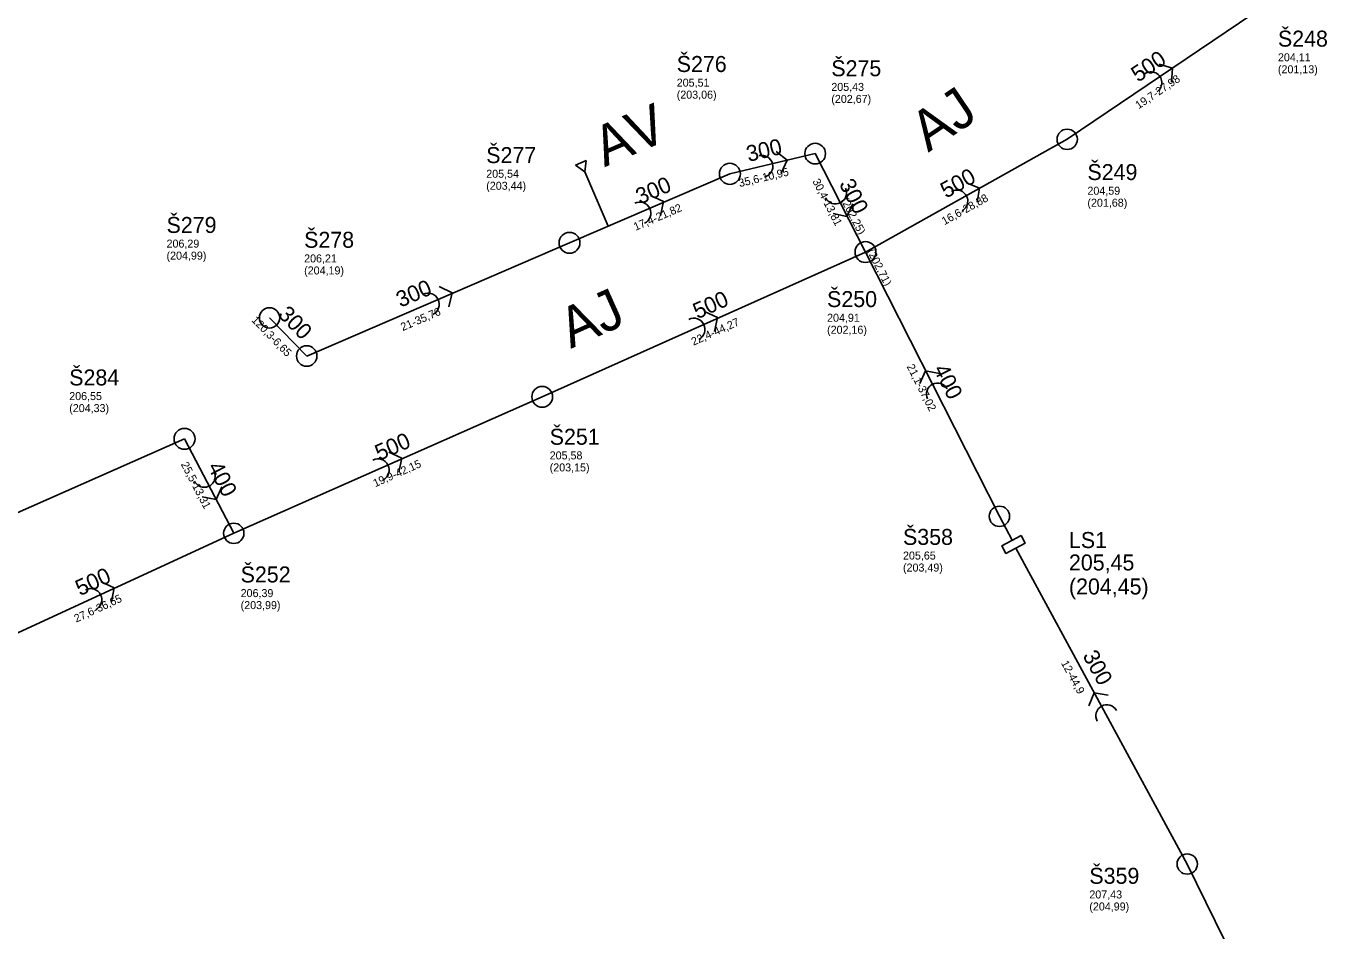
# Model space of a CAD drawing. Extents: x -574467 to -573663, y -1191209 to -1190406.
# Drawn here: x -573973 to -573810.4, y -1190808.6 to -1190695.6 of the extents above; entities that cross this region are included whole.
import ezdxf

# ---------------------------------------------------------------- set-up
doc = ezdxf.new("R2010")
doc.units = 0
for name, color, linetype in [('Vrstva 1', 7, 'Continuous'), ('Vrstva 12', 7, 'Continuous'), ('Vrstva 15', 7, 'Continuous'), ('Vrstva 29', 7, 'Continuous'), ('Vrstva 32', 7, 'Continuous'), ('Vrstva 35', 7, 'Continuous'), ('Vrstva 41', 7, 'Continuous'), ('Vrstva 44', 7, 'Continuous'), ('Vrstva 45', 7, 'Continuous'), ('Vrstva 56', 7, 'Continuous'), ('Vrstva 57', 7, 'Continuous')]:
    doc.layers.add(name, color=color, linetype=linetype)

# ---------------------------------------------------------------- blocks, each defined once
blk = doc.blocks.new('100')
at = {"layer": 'Vrstva 1'}
blk.add_circle((0, 0), 1.27, dxfattribs=at)
blk = doc.blocks.new('106')
at = {"layer": 'Vrstva 1'}
for p, q in [((1.25, 0.72), (0, 0)), ((0, 0), (1.25, -0.72)), ((1.25, -0.72), (1.25, 0.72))]:
    blk.add_line(p, q, dxfattribs=at)
blk = doc.blocks.new('86')
at = {"layer": 'Vrstva 1'}
blk.add_lwpolyline([(0.79, 1.37), (1.89, 0), (0.79, -1.38)], dxfattribs=at)
blk.add_arc((-1.37, 0), 1.37, 270, 90, dxfattribs=at)
blk = doc.blocks.new('91')
at = {"layer": 'Vrstva 1'}
blk.add_lwpolyline([(0.79, 1.37), (1.89, 0), (0.79, -1.38)], dxfattribs=at)
blk.add_arc((-1.37, 0), 1.37, 270, 90, dxfattribs=at)

msp = doc.modelspace()

# ---------------------------------------------------------------- linework, layer by layer
at = {"layer": 'Vrstva 12'}
msp.add_line((-573900.287, -1190720.566), (-573903.193, -1190713.788), dxfattribs=at)
at = {"layer": 'Vrstva 15'}
for p, q in [((-573842.91, -1190709.71), (-573819.72, -1190694.05)), ((-573868.12, -1190723.79), (-573842.91, -1190709.71)), ((-573885.07, -1190714.02), (-573874.41, -1190711.5)), ((-573874.41, -1190711.5), (-573868.12, -1190723.79)), ((-573905.11, -1190722.64), (-573885.07, -1190714.02)), ((-573937.96, -1190736.78), (-573905.11, -1190722.64)), ((-573908.528, -1190741.879), (-573868.12, -1190723.79)), ((-573851.38, -1190756.81), (-573868.12, -1190723.79)), ((-573942.607, -1190732.018), (-573937.96, -1190736.78)), ((-573947.076, -1190758.931), (-573908.528, -1190741.879)), ((-574025.44, -1190778.97), (-573953.23, -1190747.128)), ((-573953.23, -1190747.128), (-573947.076, -1190758.931)), ((-573849.777, -1190759.796), (-573851.38, -1190756.81)), ((-573980.36, -1190774.27), (-573947.076, -1190758.931)), ((-573827.9, -1190800.25), (-573849.338, -1190760.798))]:
    msp.add_line(p, q, dxfattribs=at)
msp.add_lwpolyline([(-573813.849, -1190828.881), (-573813.865, -1190828.843), (-573827.9, -1190800.25)], dxfattribs=at)
at = {"layer": 'Vrstva 32'}
msp.add_lwpolyline([(-573848.678, -1190759.212), (-573851.068, -1190760.482), (-573850.558, -1190761.442), (-573848.168, -1190760.172), (-573848.678, -1190759.212)], dxfattribs=at)

# ---------------------------------------------------------------- block references
at = {"layer": 'Vrstva 12', "xscale": 0.9999999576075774, "yscale": 0.9999999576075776, "rotation": 113.00000088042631}
msp.add_blockref('106', (-573903.193, -1190713.788), dxfattribs=at)
at = {"layer": 'Vrstva 29'}
for p, xscale, yscale, rotation in [((-573842.91, -1190709.71), 0.9999999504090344, 0.9999999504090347, -148.99999841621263), ((-573874.41, -1190711.5), 1.0169561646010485, 1.0169561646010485, 153.0239835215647), ((-573885.07, -1190714.02), 1.035124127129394, 1.0351241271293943, -157.49634583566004), ((-573905.11, -1190722.64), 1.025136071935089, 1.0251360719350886, -154.74924162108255), ((-573868.12, -1190723.79), 1.0296949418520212, 1.0296949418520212, -24.133789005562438), ((-573942.607, -1190732.018), 0.9999999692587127, 0.9999999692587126, 133.99999919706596), ((-573937.96, -1190736.78), 1.0060666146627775, 1.0060666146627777, 167.3452647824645), ((-573908.528, -1190741.879), 1.022584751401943, 1.022584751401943, -154.18102569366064), ((-573953.23, -1190747.128), 1.0316957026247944, 1.0316957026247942, 156.4154111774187), ((-573851.38, -1190756.81), 0.999999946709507, 0.999999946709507, -62.999999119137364), ((-573947.076, -1190758.931), 0.9999999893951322, 0.9999999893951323, -109.99999905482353), ((-573827.9, -1190800.25), 0.9999999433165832, 0.999999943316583, -64.0000000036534)]:
    msp.add_blockref('100', p, dxfattribs=dict(at, xscale=xscale, yscale=yscale, rotation=rotation))
at = {"layer": 'Vrstva 41'}
for name, p, xscale, yscale, rotation in [('91', (-573831.315, -1190701.88), 0.9999999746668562, 0.999999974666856, 34.00000045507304), ('86', (-573879.74, -1190712.76), 1.0028916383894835, 1.0028916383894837, 13.697207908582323), ('91', (-573855.515, -1190716.75), 1.0037041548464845, 1.0037041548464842, 29.379208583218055), ('86', (-573895.09, -1190718.33), 1.022584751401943, 1.022584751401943, 25.818974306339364), ('86', (-573871.265, -1190717.645), 0.9999999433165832, 0.999999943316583, -64.0000000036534), ('86', (-573921.535, -1190729.71), 1.022584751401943, 1.022584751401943, 25.818974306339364), ('91', (-573888.324, -1190732.834), 1.0198568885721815, 1.0198568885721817, 26.39398240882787), ('86', (-573859.75, -1190740.3), 0.999999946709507, 0.999999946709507, 117.00000088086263), ('91', (-573927.802, -1190750.405), 1.0198568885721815, 1.0198568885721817, 26.39398240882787), ('86', (-573950.153, -1190753.03), 0.999999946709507, 0.999999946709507, -62.999999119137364), ('91', (-573963.718, -1190766.601), 1.0169561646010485, 1.0169561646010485, 26.97601647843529), ('86', (-573838.619, -1190780.524), 0.999999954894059, 0.9999999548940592, 119.00000058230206)]:
    msp.add_blockref(name, p, dxfattribs=dict(at, xscale=xscale, yscale=yscale, rotation=rotation))

# ---------------------------------------------------------------- texts
at = {"layer": 'Vrstva 32'}
for s, p in [('LS1', (-573842.691, -1190760.771)), ('205,45 ', (-573842.691, -1190763.571)), ('(204,45)', (-573842.691, -1190766.571))]:
    msp.add_text(s, height=2, dxfattribs=at).set_placement(p)
at = {"layer": 'Vrstva 35'}
for s, rotation, p in [('AJ', 34.03, (-573860.278, -1190711.393)), ('AV', 23.29, (-573900.739, -1190713.208)), ('AJ', 24.12, (-573904.956, -1190735.894))]:
    msp.add_text(s, height=5, rotation=rotation, dxfattribs=at).set_placement(p)
at = {"layer": 'Vrstva 44'}
for s, rotation, p in [('500', 34.03, (-573834.054, -1190702.648)), ('300', 13.3, (-573882.743, -1190712.54)), ('300', 23.27, (-573896.303, -1190717.87)), ('300', 297.1, (-573871.466, -1190715.262)), ('500', 29.18, (-573858.041, -1190717.128)), ('300', 23.29, (-573926.241, -1190730.754)), ('500', 24.12, (-573889.121, -1190732.204)), ('300', 314.3, (-573941.656, -1190731.701)), ('400', 296.88, (-573859.686, -1190738.421)), ('500', 23.86, (-573928.876, -1190749.894)), ('400', 297.54, (-573950.4, -1190750.615)), ('500', 24.74, (-573966.293, -1190766.8)), ('300', 298.52, (-573841.029, -1190774.2))]:
    msp.add_text(s, height=2, rotation=rotation, dxfattribs=at).set_placement(p)
at = {"layer": 'Vrstva 45'}
for s, rotation, p in [('19,7-27,98', 34.03, (-573833.98, -1190705.971)), ('35,6-10,95', 13.3, (-573883.847, -1190715.682)), ('30,4-13,81', 297.1, (-573874.781, -1190714.938)), ('17,4-21,82', 23.27, (-573896.844, -1190721.151)), ('(202,25)', 297.1, (-573871.221, -1190717.289)), ('16,6-28,88', 29.18, (-573858.252, -1190720.452)), ('(202,71)', 296.88, (-573867.941, -1190723.699)), ('21-35,76', 23.29, (-573925.955, -1190733.679)), ('120,3-6,65', 314.3, (-573944.918, -1190732.37)), ('22,4-44,27', 24.12, (-573889.62, -1190735.5)), ('21,1-37,02', 296.88, (-573862.997, -1190738.089)), ('25,5-13,31', 297.54, (-573953.711, -1190750.309)), ('19,9-42,15', 23.86, (-573929.395, -1190753.185)), ('27,6-36,65', 24.74, (-573966.758, -1190770.097)), ('12-44,9', 298.52, (-573843.71, -1190775.139))]:
    msp.add_text(s, height=1, rotation=rotation, dxfattribs=at).set_placement(p)
at = {"layer": 'Vrstva 56'}
for s, p in [('204,11 ', (-573816.57, -1190699.96)), ('(201,13)', (-573816.57, -1190701.46)), ('205,51 ', (-573891.71, -1190703.13)), ('205,43 ', (-573872.39, -1190703.66)), ('(203,06)', (-573891.71, -1190704.63)), ('(202,67)', (-573872.39, -1190705.16)), ('205,54 ', (-573915.52, -1190714.51)), ('(203,44)', (-573915.52, -1190716.01)), ('204,59 ', (-573840.38, -1190716.63)), ('(201,68)', (-573840.38, -1190718.13)), ('206,29 ', (-573955.477, -1190723.238)), ('(204,99)', (-573955.477, -1190724.738)), ('206,21 ', (-573938.28, -1190725.09)), ('(204,19)', (-573938.28, -1190726.59)), ('204,91 ', (-573872.92, -1190732.5)), ('(202,16)', (-573872.92, -1190734)), ('206,55 ', (-573967.64, -1190742.288)), ('(204,33)', (-573967.64, -1190743.788)), ('205,58 ', (-573907.588, -1190749.699)), ('(203,15)', (-573907.588, -1190751.199)), ('205,65 ', (-573863.43, -1190762.21)), ('(203,49)', (-573863.43, -1190763.71)), ('206,39 ', (-573946.216, -1190766.901)), ('(203,99)', (-573946.216, -1190768.401)), ('207,43 ', (-573840.14, -1190804.55)), ('(204,99)', (-573840.14, -1190806.05))]:
    msp.add_text(s, height=1, dxfattribs=at).set_placement(p)
at = {"layer": 'Vrstva 57'}
for s, p in [('Š248', (-573816.57, -1190698.13)), ('Š276', (-573891.71, -1190701.3)), ('Š275', (-573872.39, -1190701.83)), ('Š277', (-573915.52, -1190712.68)), ('Š249', (-573840.38, -1190714.8)), ('Š279', (-573955.477, -1190721.408)), ('Š278', (-573938.28, -1190723.26)), ('Š250', (-573872.92, -1190730.67)), ('Š284', (-573967.64, -1190740.458)), ('Š251', (-573907.588, -1190747.869)), ('Š358', (-573863.43, -1190760.38)), ('Š252', (-573946.216, -1190765.071)), ('Š359', (-573840.14, -1190802.72))]:
    msp.add_text(s, height=2, dxfattribs=at).set_placement(p)

doc.saveas('drawing.dxf')
